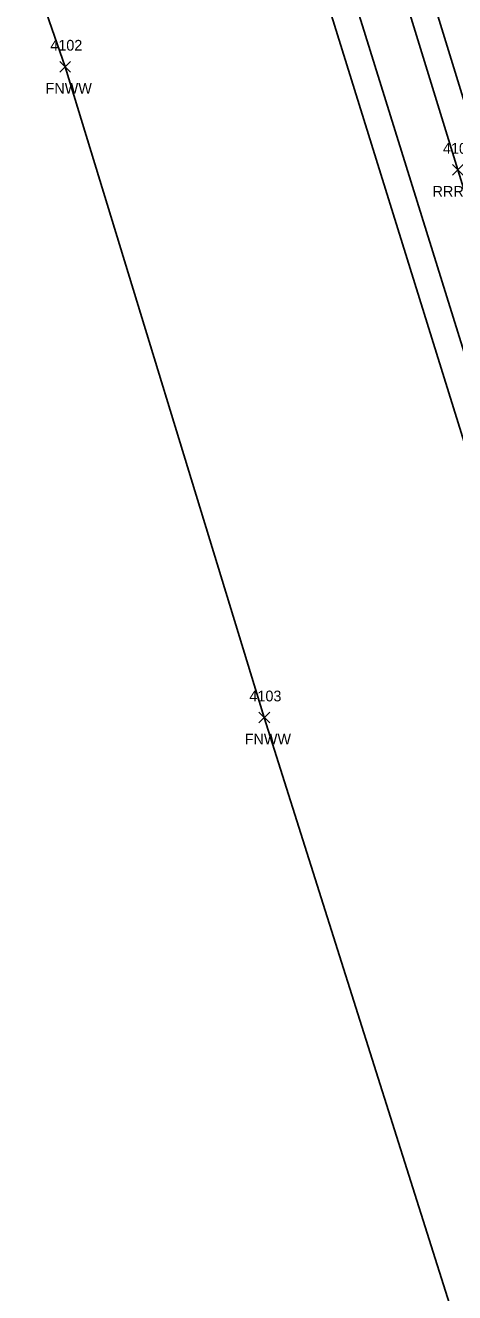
# Model space of a CAD drawing. Extents: x 1462668 to 1465147, y 550359 to 557351.
# Drawn here: x 1463479 to 1463558.8, y 555842.9 to 556078.6 of the extents above; entities that cross this region are included whole.
import ezdxf

# ---------------------------------------------------------------- set-up
doc = ezdxf.new("R2010")
doc.units = 0
for name, color, linetype in [('L_A', 7, 'Continuous'), ('L_I', 7, 'Continuous'), ('L_TIC', 7, 'Continuous'), ('LFNC', 7, 'Continuous'), ('R_A', 7, 'Continuous'), ('R_I', 7, 'Continuous'), ('R_TIC', 7, 'Continuous'), ('RR', 7, 'Continuous')]:
    doc.layers.add(name, color=color, linetype=linetype)

msp = doc.modelspace()

# ---------------------------------------------------------------- linework, layer by layer
at = {"layer": 'L_TIC'}
for points in [[(1463485.41, 556069.89), (1463487.41, 556071.89)], [(1463487.41, 556069.89), (1463485.41, 556071.89)], [(1463522.44, 555948.87), (1463524.44, 555950.87)], [(1463524.44, 555948.87), (1463522.44, 555950.87)]]:
    msp.add_lwpolyline(points, dxfattribs=at)
at = {"layer": 'LFNC'}
msp.add_lwpolyline([(1463260.37, 556856.1), (1463287.51, 556773.76), (1463336.63, 556617.91), (1463317.04, 556611.87), (1463340, 556536.42), (1463360.93, 556468), (1463386.6, 556387.45), (1463412.74, 556299.98), (1463432.82, 556224.94), (1463450.92, 556180.39), (1463467.13, 556126.19), (1463486.41, 556070.89), (1463523.44, 555949.87), (1463564.29, 555820.42)], dxfattribs=at)
at = {"layer": 'R_TIC'}
for points in [[(1463558.44, 556050.72), (1463560.44, 556052.72)], [(1463560.44, 556050.72), (1463558.44, 556052.72)], [(1463558.44, 556050.72), (1463560.44, 556052.72)], [(1463560.44, 556050.72), (1463558.44, 556052.72)]]:
    msp.add_lwpolyline(points, dxfattribs=at)
at = {"layer": 'RR'}
for points in [[(1463452.29, 556399.95), (1463497.45, 556252.55), (1463536.87, 556125.13), (1463559.44, 556051.72), (1463609.03, 555892.1), (1463628.98, 555828.76), (1463638.23, 555801.69), (1463650.08, 555771.85), (1463660.17, 555749.93), (1463672.27, 555721.97), (1463682.4, 555694.55), (1463717.94, 555583.41), (1463735.76, 555525.64), (1463763.54, 555435.87), (1463784.43, 555367.81), (1463820.27, 555252.31), (1463843.81, 555175.84), (1463843.97, 555175.21), (1463873.04, 555081.28), (1463903.09, 554986.35)], [(1463457.08, 556400.94), (1463502.23, 556254.01), (1463520.47, 556194.57), (1463541.51, 556126.54), (1463564.15, 556052.98), (1463586.06, 555983.65), (1463613.76, 555893.64), (1463633.52, 555829.96), (1463642.44, 555804.5), (1463654.17, 555774.55), (1463664.49, 555752.05), (1463676.6, 555724.22), (1463687.08, 555696.18), (1463722.45, 555584.97), (1463740.37, 555527.27), (1463768.14, 555437.45), (1463788.82, 555369.5), (1463824.75, 555254.42), (1463848.38, 555177.53), (1463848.44, 555177), (1463877.95, 555082.45), (1463907.74, 554987.88)], [(1463442.74, 556395.94), (1463488.6, 556249.11), (1463529.74, 556117.02), (1463572.82, 555978.5), (1463585.63, 555937.65), (1463596.03, 555904.23), (1463633.49, 555784.66), (1463672.64, 555658.35), (1463710.59, 555536.66), (1463747.52, 555418.1), (1463780.06, 555313.88), (1463826.09, 555167.8), (1463825.99, 555167.57), (1463854.77, 555075.73), (1463884.96, 554978.2)], [(1463438.37, 556393.48), (1463483.91, 556247.77), (1463525.3, 556114.77), (1463568.13, 555976.96), (1463580.9, 555936.2), (1463591.21, 555903.11), (1463628.7, 555782.9), (1463668.19, 555656.69), (1463705.56, 555535.16), (1463742.77, 555417.12), (1463775.39, 555312.32), (1463821.31, 555166.17), (1463821.55, 555165.37), (1463850.06, 555074.38), (1463880.04, 554977.58)]]:
    msp.add_lwpolyline(points, dxfattribs=at)

# ---------------------------------------------------------------- texts
at = {"layer": 'L_A'}
for p in [(1463482.76, 556065.89), (1463519.79, 555944.87)]:
    msp.add_text('FNWW', height=2, dxfattribs=at).set_placement(p)
at = {"layer": 'L_I'}
for s, p in [('4102', (1463483.64, 556073.89)), ('4103', (1463520.67, 555952.87))]:
    msp.add_text(s, height=2, dxfattribs=at).set_placement(p)
at = {"layer": 'R_A'}
msp.add_text('RRRAIL', height=2, dxfattribs=at).set_placement((1463554.73, 556046.72))
msp.add_text('RRRAIL', height=2, dxfattribs=at).set_placement((1463554.73, 556046.72))
at = {"layer": 'R_I'}
msp.add_text('4107', height=2, dxfattribs=at).set_placement((1463556.66, 556054.72))
msp.add_text('4107', height=2, dxfattribs=at).set_placement((1463556.66, 556054.72))

doc.saveas('drawing.dxf')
